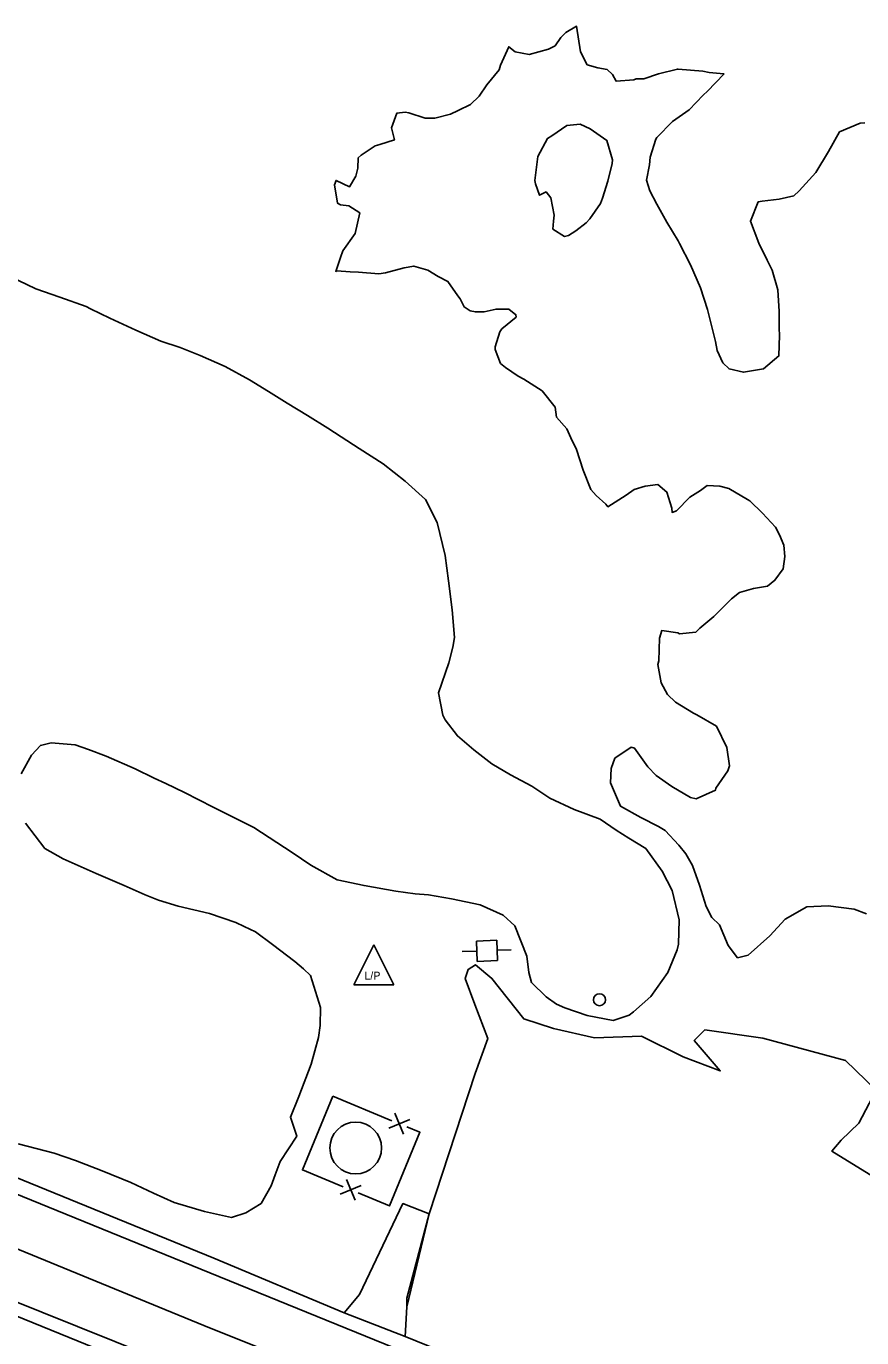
# Model space of a CAD drawing. Extents: x 2160437 to 2172832, y 205694 to 212444.
# Drawn here: x 2164009 to 2164217.8, y 210144.2 to 210471.9 of the extents above; entities that cross this region are included whole.
import ezdxf

# ---------------------------------------------------------------- set-up
doc = ezdxf.new("R2010")
doc.units = 0
for name, color, linetype in [('Default', 7, 'Continuous'), ('RD_EX_Bldg', 7, 'Continuous'), ('RD_EX_Driveway', 7, 'Continuous'), ('RD_EX_Fence_Other', 7, 'Continuous'), ('RD_EX_LaneStripe', 7, 'Continuous'), ('RD_EX_Road', 7, 'Continuous'), ('RD_EX_Road_Post', 7, 'Continuous'), ('RD_EX_UT', 7, 'Continuous'), ('RD_EX_VEG_ShrubLine', 7, 'Continuous'), ('RD_EX_VEG_TreeLine', 7, 'Continuous')]:
    doc.layers.add(name, color=color, linetype=linetype)

# ---------------------------------------------------------------- blocks, each defined once
blk = doc.blocks.new('RD_EX_Fnce_Other')
at = {"layer": 'Default'}
for points in [[(-0.0417, -0.0417), (0.0417, 0.0417)], [(-0.0417, 0.0417), (0.0417, -0.0417)]]:
    blk.add_lwpolyline(points, dxfattribs=at)
blk = doc.blocks.new('POST')
at = {"layer": 'Default'}
for start, end in [(90, 270), (270, 90)]:
    blk.add_arc((0, 0), 0.0417, start, end, dxfattribs=at)
blk = doc.blocks.new('PP')
at = {"layer": 'RD_EX_UT'}
for p, q in [((2.49, 2.51), (-2.51, 2.51)), ((-2.51, 2.51), (-2.51, -2.49)), ((2.49, -2.49), (2.49, 2.51)), ((-5.94, -0.05), (-2.47, -0.05)), ((-2.51, -2.49), (2.49, -2.49)), ((2.42, -0.05), (6.06, -0.05))]:
    blk.add_line(p, q, dxfattribs=at)

msp = doc.modelspace()

# ---------------------------------------------------------------- linework, layer by layer
at = {"layer": 'RD_EX_Bldg'}
msp.add_circle((2164091.32, 210191.57), 6.47, dxfattribs=at)
at = {"layer": 'RD_EX_Driveway'}
msp.add_lwpolyline([(2164088.45, 210150.38), (2164092.3, 210154.96), (2164103.14, 210177.66), (2164109.68, 210175.1), (2164104.13, 210154.06), (2164104.13, 210151.9), (2164103.67, 210144.43)], dxfattribs=at)
at = {"layer": 'RD_EX_Fence_Other'}
for points in [[(2164088.23, 210181.87), (2164078, 210186.08), (2164085.58, 210204.5)], [(2164085.58, 210204.5), (2164100.38, 210198.4)], [(2164104.07, 210196.88), (2164107.38, 210195.52), (2164099.8, 210177.1), (2164091.93, 210180.35)]]:
    msp.add_lwpolyline(points, dxfattribs=at)
at = {"layer": 'RD_EX_LaneStripe'}
for points in [[(2163344.27, 210436.03), (2163414.73, 210407.45), (2163485.82, 210378.43), (2163557.41, 210349.54), (2163630.41, 210319.67), (2163698.64, 210291.57), (2163771.09, 210262.33), (2163842.32, 210233.17), (2163913.26, 210204.34), (2163984.85, 210175.29), (2164053.38, 210147.25)], [(2164053.38, 210147.25), (2164123.11, 210119.29), (2164196.85, 210089.22), (2164265.56, 210061.12), (2164336.65, 210032.35), (2164405.58, 210004.27), (2164479.64, 209974.11), (2164550.79, 209945.02), (2164618.79, 209917.14), (2164687.93, 209889.27), (2164713.96, 209878.5)]]:
    msp.add_lwpolyline(points, dxfattribs=at)
at = {"layer": 'RD_EX_Road'}
for points in [[(2164055.87, 210164.02), (2164004.08, 210185.19), (2163920.58, 210219.36), (2163847.91, 210248.65), (2163765.58, 210282.06), (2163649.55, 210329.02), (2163593.64, 210352.21), (2163517.08, 210383.78), (2163430.92, 210418.42), (2163348.93, 210451.8)], [(2164054.87, 210160.36), (2163971.94, 210194.13), (2163868.37, 210236.26), (2163770.62, 210275.93), (2163648.21, 210325.87), (2163554.92, 210364.19), (2163463.65, 210401.3), (2163347.49, 210448.15)], [(2163339.36, 210424.64), (2163420.98, 210391.42), (2163497.03, 210360.67), (2163575.97, 210328.25), (2163667.7, 210290.66), (2163742.47, 210260.32), (2163822.04, 210228.09), (2163909.42, 210192.51), (2163985.2, 210161.6), (2164049.4, 210135.92)], [(2163337.83, 210421.74), (2163444.25, 210378.23), (2163530.28, 210343.44), (2163596.65, 210315.89), (2163680.6, 210281.31), (2163754.64, 210251.65), (2163815.16, 210227.17), (2163865.96, 210206.52), (2163934.01, 210179.08), (2164048.1, 210132.64)], [(2164719.32, 209893.53), (2164711.43, 209896.75), (2164660.02, 209917.67), (2164574.62, 209952.59), (2164515.44, 209976.77), (2164441.71, 210006.87), (2164361.41, 210039.86), (2164286.82, 210070.11), (2164199.81, 210105.86), (2164140.4, 210129.54), (2164103.67, 210144.43), (2164088.45, 210150.38), (2164055.87, 210164.02)], [(2164054.87, 210160.36), (2164149.67, 210121.83), (2164199.63, 210101.52), (2164285.68, 210066.64), (2164373.04, 210031.13), (2164462.58, 209994.39), (2164557.26, 209955.73), (2164630.42, 209925.95), (2164717.47, 209890.02)]]:
    msp.add_lwpolyline(points, dxfattribs=at)
at = {"layer": 'RD_EX_UT'}
for p, q in [((2164090.89, 210232.36), (2164095.89, 210242.36)), ((2164095.89, 210242.36), (2164100.89, 210232.36)), ((2164090.89, 210232.36), (2164100.89, 210232.36))]:
    msp.add_line(p, q, dxfattribs=at)
at = {"layer": 'RD_EX_VEG_ShrubLine'}
for points in [[(2164137.93, 210380.78), (2164133.31, 210383.7), (2164131.89, 210384.41), (2164128.75, 210386.6), (2164127.47, 210387.64), (2164126.15, 210391.06), (2164126.15, 210391.78), (2164127.34, 210395.51), (2164127.82, 210396.25), (2164131.43, 210399.22), (2164131.37, 210399.8), (2164129.6, 210401.14), (2164126.4, 210401.22), (2164123.39, 210400.5), (2164121.26, 210400.5), (2164119.89, 210400.79), (2164118.42, 210401.76), (2164117.4, 210403.72), (2164116.81, 210404.53), (2164114.38, 210408.13), (2164111.93, 210409.38), (2164109.31, 210410.94), (2164105.81, 210411.94), (2164103.4, 210411.5), (2164098.81, 210410.23), (2164097.14, 210410.02), (2164092.02, 210410.4), (2164089.94, 210410.53), (2164086.64, 210410.73), (2164086.35, 210410.62), (2164087.51, 210414.13), (2164088.08, 210415.78), (2164091.18, 210420.09), (2164091.18, 210420.09), (2164092.37, 210425.25), (2164092.37, 210425.25), (2164089.6, 210427.02), (2164087.49, 210427.25), (2164086.79, 210427.64), (2164086, 210432.25), (2164086.4, 210433.34), (2164089.81, 210431.75), (2164091.36, 210434.38), (2164091.88, 210436.44), (2164091.9, 210438.96), (2164092.67, 210439.64), (2164096.18, 210442.03), (2164097.33, 210442.31), (2164101.02, 210443.51), (2164100.27, 210446.45), (2164100.27, 210446.45), (2164101.59, 210450.13), (2164103.68, 210450.39), (2164104.56, 210450.23), (2164108.72, 210448.94), (2164111.08, 210448.92), (2164115.01, 210449.94), (2164116.97, 210450.8), (2164120.01, 210452.3), (2164122.2, 210454.41), (2164124.11, 210457.27), (2164127.17, 210460.97), (2164127.53, 210462.15), (2164129.58, 210466.76), (2164129.58, 210466.76), (2164131.16, 210465.51), (2164134.65, 210464.83), (2164134.65, 210464.83), (2164139.5, 210466.16), (2164141.14, 210467.01), (2164142.6, 210469.04), (2164143.8, 210470.33), (2164146.54, 210471.88), (2164147.48, 210465.46), (2164147.48, 210465.46), (2164149.21, 210462.24), (2164151.86, 210461.46), (2164154.14, 210461.08), (2164155.49, 210459.85), (2164156.41, 210458.18), (2164160.82, 210458.51), (2164161.39, 210458.73), (2164163.36, 210458.72), (2164166.99, 210459.96), (2164171.71, 210461.18), (2164171.94, 210461.15), (2164178.04, 210460.66), (2164179.7, 210460.31), (2164183.34, 210459.97), (2164183.31, 210459.9), (2164179.21, 210455.64), (2164178.15, 210454.69), (2164174.64, 210451.03), (2164170.48, 210448.06), (2164166.56, 210444.04), (2164166.32, 210443.67), (2164164.94, 210439.15), (2164164.74, 210437.27), (2164163.98, 210433.42), (2164164.84, 210430.75), (2164166.61, 210427.43), (2164166.61, 210427.43), (2164169.11, 210422.93), (2164169.11, 210422.93), (2164171.94, 210418.28), (2164172.27, 210417.58)], [(2164218.6, 210447.76), (2164217.41, 210447.63), (2164212.25, 210445.49), (2164212.25, 210445.49), (2164209.48, 210440.61), (2164206.3, 210435.37), (2164206.3, 210435.37), (2164202.19, 210430.73), (2164200.79, 210429.49), (2164197.2, 210428.69), (2164192.88, 210428.16), (2164191.91, 210427.99), (2164189.99, 210423.15), (2164189.99, 210423.15), (2164192.05, 210417.67), (2164194.12, 210413.45), (2164195.39, 210410.91), (2164196.85, 210405.99), (2164197.19, 210400.56), (2164197.16, 210396.32), (2164197.25, 210394.66), (2164197.11, 210389.5), (2164197.11, 210389.5), (2164193.23, 210386.31), (2164193.23, 210386.31), (2164188.22, 210385.43), (2164184.63, 210386.25), (2164183.04, 210387.8), (2164181.65, 210390.88), (2164181.21, 210393.12), (2164179.24, 210401.07), (2164177.53, 210406.51), (2164175, 210412.26), (2164175, 210412.26), (2164172.27, 210417.58)], [(2164137.93, 210380.78), (2164141.21, 210376.69), (2164141.21, 210376.69), (2164141.54, 210374.2), (2164144.07, 210371.27), (2164145.12, 210369.06), (2164146.52, 210366.15), (2164148.2, 210360.91), (2164148.2, 210360.91), (2164150.08, 210356.11), (2164151.4, 210354.62), (2164153.8, 210352.47), (2164154.34, 210351.81), (2164158.95, 210354.74), (2164160.89, 210356.15), (2164163.65, 210356.95), (2164166.83, 210357.34), (2164169.11, 210355.48), (2164170.37, 210351.44), (2164170.39, 210350.41), (2164171.48, 210350.82), (2164174.86, 210354.24), (2164177.51, 210355.87), (2164179.19, 210357.1), (2164182.31, 210356.97), (2164184.55, 210356.33), (2164189.23, 210353.64), (2164189.79, 210353.27), (2164192.96, 210350.18), (2164196.26, 210346.67), (2164197.27, 210344.78), (2164198.29, 210342.22), (2164198.57, 210339.34), (2164198.16, 210336.28), (2164196.11, 210333.42), (2164194.21, 210331.99), (2164190.75, 210331.37), (2164187.26, 210330.41), (2164185.27, 210328.77), (2164181.33, 210324.9), (2164180.81, 210324.41), (2164177.33, 210321.46), (2164176.3, 210320.48), (2164172.22, 210320.08), (2164171.82, 210320.26), (2164167.84, 210320.9), (2164167.22, 210318.95), (2164167.05, 210313.33), (2164166.8, 210312.36), (2164167.69, 210307.77), (2164169.29, 210304.9), (2164171.26, 210303), (2164175.72, 210300.23), (2164176.6, 210299.77), (2164181.48, 210297), (2164184.07, 210291.64), (2164184.71, 210287.04), (2164184.35, 210285.82), (2164181.33, 210281.47), (2164181.23, 210280.97), (2164176.44, 210278.85), (2164175.01, 210279.13), (2164170.37, 210281.92), (2164166.43, 210284.64), (2164164.34, 210286.83), (2164161.02, 210291.49), (2164160.13, 210291.77), (2164156.06, 210288.96), (2164155.17, 210286.42), (2164155, 210282.83), (2164157.49, 210276.99), (2164157.49, 210276.99), (2164162.57, 210274.12), (2164167.04, 210271.89), (2164168.63, 210270.88), (2164172.12, 210267.28), (2164173.84, 210265.08), (2164175.48, 210262.18), (2164177.22, 210257.21), (2164177.22, 210257.21), (2164178.93, 210251.89), (2164180.3, 210249.18), (2164182.22, 210247.3), (2164184.41, 210242.13), (2164184.41, 210242.13), (2164186.78, 210239.09), (2164189.37, 210239.79), (2164194.8, 210244.57), (2164194.8, 210244.57), (2164198.66, 210248.78), (2164204.04, 210251.84), (2164204.04, 210251.84), (2164209.38, 210252.1), (2164215.94, 210251.22), (2164218.98, 210250.1)]]:
    msp.add_lwpolyline(points, dxfattribs=at)
msp.add_lwpolyline([(2164136.82, 210439.31), (2164139.23, 210443.85), (2164140.3, 210444.48), (2164144.13, 210447.05), (2164147.44, 210447.39), (2164149.94, 210446.28), (2164154.09, 210443.34), (2164154.09, 210443.34), (2164155.48, 210438.46), (2164155.39, 210437.55), (2164154.3, 210433.14), (2164152.97, 210428.91), (2164152.48, 210427.62), (2164149.88, 210423.72), (2164148.9, 210422.74), (2164146.34, 210420.72), (2164144.49, 210419.57), (2164143.53, 210419.36), (2164140.63, 210421.2), (2164140.73, 210423.21), (2164140.92, 210424.7), (2164140.05, 210428.96), (2164138.91, 210430.49), (2164137.27, 210429.64), (2164136.26, 210432.53), (2164136.13, 210433.3)], close=True, dxfattribs=at)
at = {"layer": 'RD_EX_VEG_TreeLine'}
for points in [[(2164004.92, 210409.32), (2164011.36, 210406.23), (2164017.34, 210404.21), (2164023.94, 210401.83), (2164025.03, 210401.26), (2164029.85, 210398.97), (2164036.39, 210395.91), (2164042.62, 210393.22), (2164047.42, 210391.57), (2164052.48, 210389.64), (2164058.68, 210386.88), (2164064.75, 210383.48), (2164069.54, 210380.57), (2164074.16, 210377.65), (2164079.31, 210374.65), (2164084.37, 210371.46), (2164087.73, 210369.25), (2164092.19, 210366.33), (2164098.18, 210362.56), (2164103.68, 210358.23), (2164108.74, 210353.61), (2164108.74, 210353.61), (2164111.65, 210347.9), (2164111.65, 210347.9), (2164113.68, 210339.66), (2164114.49, 210333.3), (2164115.47, 210326.07), (2164116.02, 210319.12), (2164115.58, 210316.71), (2164114.63, 210312.79), (2164112.03, 210305.33), (2164113.1, 210299.73), (2164113.7, 210298.59), (2164116.73, 210294.56), (2164120.86, 210291.07), (2164125.32, 210287.59), (2164125.32, 210287.59), (2164130, 210284.8), (2164135.37, 210281.95), (2164139.83, 210279.02), (2164139.83, 210279.02), (2164145.91, 210276.17), (2164152.42, 210273.75), (2164156.39, 210270.96), (2164159.55, 210269.01), (2164163.84, 210266.39), (2164167.88, 210260.73), (2164170.39, 210255.9), (2164170.39, 210255.9), (2164172.19, 210248.55), (2164172.04, 210242.54), (2164171.63, 210241.06), (2164169.37, 210235.44), (2164165.12, 210229.42), (2164160.74, 210225.6), (2164159.65, 210224.75), (2164155.67, 210223.43), (2164149.21, 210224.72), (2164143.63, 210226.56), (2164141.52, 210227.5), (2164138.95, 210229.35), (2164135.26, 210232.96), (2164134.63, 210235.45), (2164134.12, 210239.47), (2164131.09, 210247.05), (2164128.19, 210249.76), (2164122.45, 210252.31), (2164115.24, 210253.85), (2164109.51, 210254.81), (2164106.17, 210255.11), (2164101.39, 210255.73), (2164093.41, 210257.14), (2164086.71, 210258.61), (2164086.71, 210258.61), (2164080.12, 210262.25), (2164075.45, 210265.43), (2164065.82, 210271.67), (2164055.67, 210276.73), (2164048.52, 210280.38), (2164043.86, 210282.68), (2164040.96, 210283.97), (2164036.23, 210286.3), (2164028.98, 210289.52), (2164024.57, 210291.16), (2164021.22, 210292.33), (2164015.19, 210292.8), (2164012.54, 210292.16), (2164010.26, 210289.7), (2164007.73, 210285.06)], [(2164008.81, 210272.73), (2164013.66, 210266.4), (2164018.2, 210263.83), (2164018.2, 210263.83), (2164026.45, 210260.17), (2164033.47, 210257.13), (2164038.68, 210254.82), (2164042.04, 210253.49), (2164046.99, 210252), (2164054.76, 210250.13), (2164061.36, 210247.91), (2164063.44, 210246.91), (2164066.31, 210245.56), (2164070.53, 210242.42), (2164076.15, 210238.19), (2164078.27, 210236.38), (2164080.03, 210234.65), (2164082.5, 210226.69), (2164082.48, 210222.2), (2164082, 210219.17), (2164080.17, 210212.56), (2164077.12, 210204.44), (2164075, 210199.3), (2164076.58, 210194.49), (2164072.44, 210188.2), (2164071.21, 210184.88), (2164070.23, 210182.15), (2164067.69, 210177.67), (2164063.89, 210175.33), (2164060.29, 210174.17), (2164053.57, 210175.73), (2164053.57, 210175.73), (2164045.94, 210177.93), (2164040.75, 210180.31), (2164040.75, 210180.31), (2164035.14, 210182.96), (2164027.99, 210185.89), (2164021.32, 210188.46), (2164015.97, 210190.28), (2164006.97, 210192.62)], [(2164140.4, 210129.54), (2164103.67, 210144.43), (2164104.13, 210151.9), (2164109.68, 210175.1), (2164121.2, 210210.21), (2164124.32, 210218.96), (2164121.13, 210227.4), (2164118.64, 210233.91), (2164119.47, 210236.18), (2164121.23, 210237.31), (2164125.38, 210233.96), (2164133.33, 210223.82), (2164140.77, 210221.4), (2164151.02, 210219.1), (2164162.77, 210219.5), (2164173.13, 210214.34), (2164182.43, 210210.85), (2164175.92, 210218.44), (2164178.59, 210221.08), (2164193.1, 210219.05), (2164213.7, 210213.46), (2164221.41, 210206), (2164217.09, 210197.79), (2164212.62, 210193.55), (2164210.31, 210190.79), (2164227.2, 210180.38)]]:
    msp.add_lwpolyline(points, dxfattribs=at)

# ---------------------------------------------------------------- block references
at = {"layer": 'RD_EX_Fence_Other'}
for p, xscale, yscale, rotation in [((2164102.22, 210197.64), 47.999999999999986, 48.00000000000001, -22.384101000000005), ((2164090.08, 210181.11), 48, 48, 157.615899)]:
    msp.add_blockref('RD_EX_Fnce_Other', p, dxfattribs=dict(at, xscale=xscale, yscale=yscale, rotation=rotation))
at = {"layer": 'RD_EX_Road_Post', "xscale": 36, "yscale": 36}
msp.add_blockref('POST', (2164152.25, 210228.62), dxfattribs=at)
at = {"layer": 'RD_EX_UT', "xscale": 1.0199999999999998, "yscale": 1.0199999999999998, "rotation": -177.75438600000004}
msp.add_blockref('PP', (2164124.13, 210240.84), dxfattribs=at)

# ---------------------------------------------------------------- texts
at = {"layer": 'RD_EX_UT'}
msp.add_text('L/P', height=2, dxfattribs=at).set_placement((2164093.49, 210233.64))

doc.saveas('drawing.dxf')
